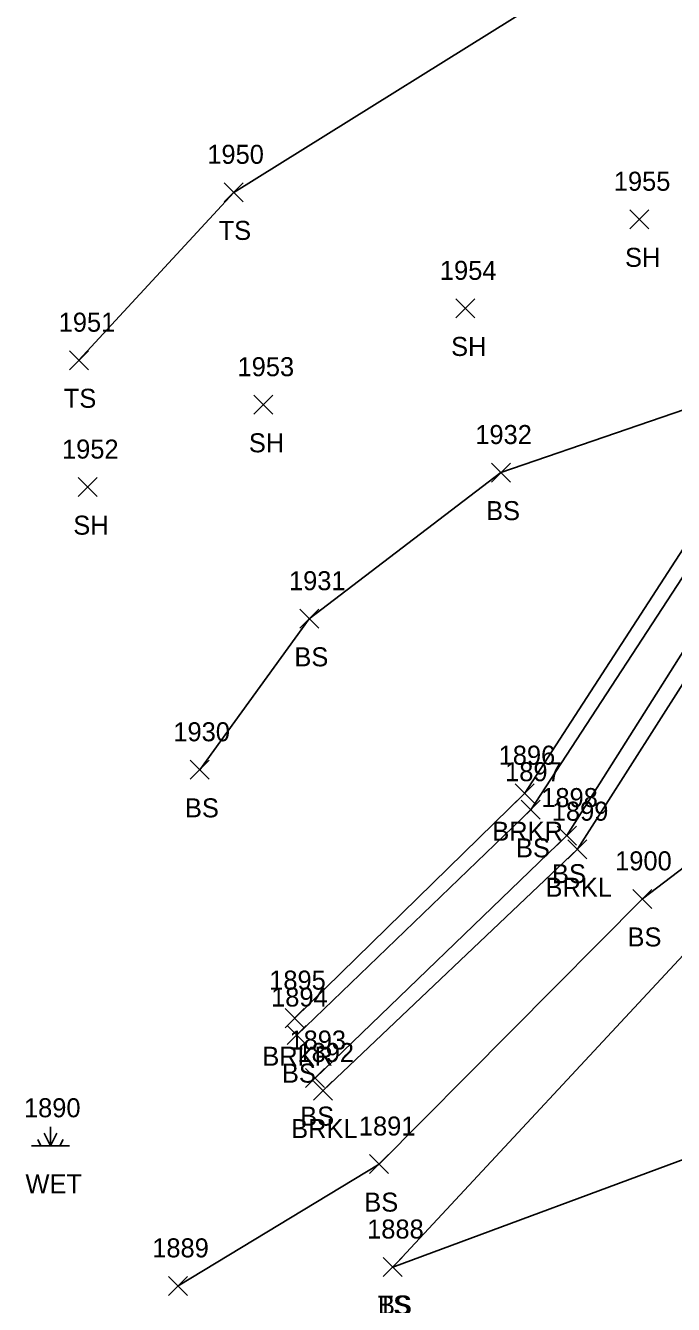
# Model space of a CAD drawing. Extents: x 1885914 to 1887218, y 756253 to 760620.
# Drawn here: x 1886288.7 to 1886356.8, y 759652.9 to 759787.4 of the extents above; entities that cross this region are included whole.
import ezdxf

# ---------------------------------------------------------------- set-up
doc = ezdxf.new("R2010")
doc.units = 0
for name, color, linetype in [('L_A', 7, 'Continuous'), ('L_I', 7, 'Continuous'), ('L_TIC', 7, 'Continuous'), ('LAWE', 7, 'Continuous'), ('LELB', 7, 'Continuous'), ('LWET', 7, 'Continuous')]:
    doc.layers.add(name, color=color, linetype=linetype)

msp = doc.modelspace()

# ---------------------------------------------------------------- linework, layer by layer
at = {"layer": 'L_TIC'}
for points in [[(1886309.58, 759768.85), (1886311.58, 759770.85)], [(1886311.58, 759768.85), (1886309.58, 759770.85)], [(1886352.25, 759766.02), (1886354.25, 759768.02)], [(1886354.25, 759766.02), (1886352.25, 759768.02)], [(1886333.95, 759756.65), (1886335.95, 759758.65)], [(1886335.95, 759756.65), (1886333.95, 759758.65)], [(1886293.3, 759751.2), (1886295.3, 759753.2)], [(1886295.3, 759751.2), (1886293.3, 759753.2)], [(1886312.68, 759746.52), (1886314.68, 759748.52)], [(1886314.68, 759746.52), (1886312.68, 759748.52)], [(1886337.68, 759739.39), (1886339.68, 759741.39)], [(1886339.68, 759739.39), (1886337.68, 759741.39)], [(1886294.22, 759737.86), (1886296.22, 759739.86)], [(1886296.22, 759737.86), (1886294.22, 759739.86)], [(1886317.52, 759724.02), (1886319.52, 759726.02)], [(1886319.52, 759724.02), (1886317.52, 759726.02)], [(1886306, 759708.14), (1886308, 759710.14)], [(1886308, 759708.14), (1886306, 759710.14)], [(1886340.18, 759705.68), (1886342.18, 759707.68)], [(1886342.18, 759705.68), (1886340.18, 759707.68)], [(1886340.81, 759703.94), (1886342.81, 759705.94)], [(1886342.81, 759703.94), (1886340.81, 759705.94)], [(1886344.61, 759701.22), (1886346.61, 759703.22)], [(1886346.61, 759701.22), (1886344.61, 759703.22)], [(1886345.73, 759699.79), (1886347.73, 759701.79)], [(1886347.73, 759699.79), (1886345.73, 759701.79)], [(1886352.55, 759694.57), (1886354.55, 759696.57)], [(1886354.55, 759694.57), (1886352.55, 759696.57)], [(1886316, 759682.03), (1886318, 759684.03)], [(1886318, 759682.03), (1886316, 759684.03)], [(1886316.21, 759680.25), (1886318.21, 759682.25)], [(1886318.21, 759680.25), (1886316.21, 759682.25)], [(1886318.13, 759675.73), (1886320.13, 759677.73)], [(1886320.13, 759675.73), (1886318.13, 759677.73)], [(1886318.97, 759674.42), (1886320.97, 759676.42)], [(1886320.97, 759674.42), (1886318.97, 759676.42)], [(1886324.87, 759666.69), (1886326.87, 759668.69)], [(1886326.87, 759666.69), (1886324.87, 759668.69)], [(1886326.3, 759655.86), (1886328.3, 759657.86)], [(1886328.3, 759655.86), (1886326.3, 759657.86)], [(1886326.3, 759655.86), (1886328.3, 759657.86)], [(1886328.3, 759655.86), (1886326.3, 759657.86)], [(1886303.72, 759653.88), (1886305.72, 759655.88)], [(1886305.72, 759653.88), (1886303.72, 759655.88)]]:
    msp.add_lwpolyline(points, dxfattribs=at)
at = {"layer": 'LAWE'}
for points in [[(1886317, 759683.03), (1886341.18, 759706.68), (1886360.29, 759736.17), (1886364.88, 759738.76), (1886370.21, 759737.83), (1886375.31, 759734.04), (1886391.66, 759750.79), (1886399.84, 759751.25), (1886405.16, 759747.14)], [(1886319.97, 759675.42), (1886346.73, 759700.79), (1886366.11, 759731.21), (1886375.2, 759726.91), (1886379.74, 759726.02), (1886393.91, 759741.19), (1886401.85, 759738.99)]]:
    msp.add_lwpolyline(points, dxfattribs=at)
at = {"layer": 'LELB'}
for points in [[(1886420.59, 759830.9), (1886395.58, 759812.74), (1886365.13, 759802.51), (1886347.14, 759792.66), (1886310.58, 759769.85), (1886294.3, 759752.2)], [(1886307, 759709.14), (1886318.52, 759725.02), (1886338.68, 759740.39), (1886365.24, 759749.52), (1886380.86, 759754.85), (1886394.35, 759762.41), (1886406.37, 759774.36), (1886414.51, 759783.7), (1886422.61, 759797.12), (1886430.75, 759808.98)], [(1886317.21, 759681.25), (1886341.81, 759704.94), (1886361.48, 759735.07), (1886365.13, 759737.99), (1886369.88, 759736.88), (1886375.93, 759732.56), (1886392.43, 759748.73), (1886399.75, 759749.71), (1886405.53, 759745.98)], [(1886319.13, 759676.73), (1886345.61, 759702.22), (1886365.08, 759732.99), (1886376.94, 759728.59), (1886392.47, 759742.78), (1886404.87, 759741.44), (1886405.53, 759745.98)], [(1886304.72, 759654.88), (1886325.87, 759667.69), (1886353.55, 759695.57), (1886377.7, 759713.93), (1886397.18, 759731.7), (1886401.85, 759738.99)], [(1886401.43, 759725.45), (1886391.73, 759716.93), (1886382.2, 759702.66), (1886359.74, 759691.68), (1886327.3, 759656.86)], [(1886359.74, 759691.68), (1886361.34, 759669.47), (1886327.3, 759656.86)]]:
    msp.add_lwpolyline(points, dxfattribs=at)
at = {"layer": 'LWET'}
for p, q in [((1886291.3, 759669.61), (1886290.63, 759670.95)), ((1886291.3, 759669.61), (1886291.3, 759671.61)), ((1886291.3, 759669.61), (1886291.97, 759670.95)), ((1886293.3, 759669.61), (1886289.3, 759669.61)), ((1886290.3, 759669.61), (1886289.97, 759670.28)), ((1886292.3, 759669.61), (1886292.63, 759670.28))]:
    msp.add_line(p, q, dxfattribs=at)

# ---------------------------------------------------------------- texts
at = {"layer": 'L_A'}
for s, p in [('TS', (1886308.99, 759764.85)), ('SH', (1886351.73, 759762.02)), ('SH', (1886333.44, 759752.65)), ('TS', (1886292.71, 759747.2)), ('SH', (1886312.17, 759742.52)), ('BS', (1886337.12, 759735.39)), ('SH', (1886293.71, 759733.86)), ('BS', (1886316.96, 759720.02)), ('BS', (1886305.45, 759704.14)), ('BRKR', (1886337.77, 759701.68)), ('BS', (1886340.26, 759699.94)), ('BS', (1886344.05, 759697.22)), ('BRKL', (1886343.37, 759695.79)), ('BS', (1886351.99, 759690.57)), ('BRKR', (1886313.59, 759678.03)), ('BS', (1886315.65, 759676.25)), ('BS', (1886317.57, 759671.73)), ('BRKL', (1886316.62, 759670.42)), ('WET', (1886288.68, 759664.61)), ('BS', (1886324.31, 759662.69)), ('TS', (1886325.71, 759651.86)), ('BS', (1886325.75, 759651.86))]:
    msp.add_text(s, height=2, dxfattribs=at).set_placement(p)
at = {"layer": 'L_I'}
for s, p in [('1950', (1886307.8, 759772.85)), ('1955', (1886350.55, 759770.02)), ('1954', (1886332.26, 759760.65)), ('1951', (1886292.17, 759755.2)), ('1953', (1886310.98, 759750.52)), ('1932', (1886335.98, 759743.39)), ('1952', (1886292.52, 759741.86)), ('1931', (1886316.39, 759728.02)), ('1930', (1886304.23, 759712.14)), ('1896', (1886338.44, 759709.68)), ('1897', (1886339.12, 759707.94)), ('1898', (1886342.92, 759705.22)), ('1899', (1886344.03, 759703.79)), ('1900', (1886350.69, 759698.57)), ('1895', (1886314.31, 759686.03)), ('1894', (1886314.51, 759684.25)), ('1893', (1886316.44, 759679.73)), ('1892', (1886317.28, 759678.42)), ('1890', (1886288.52, 759672.61)), ('1891', (1886323.74, 759670.69)), ('1888', (1886324.61, 759659.86)), ('1888', (1886324.61, 759659.86)), ('1889', (1886302.01, 759657.88))]:
    msp.add_text(s, height=2, dxfattribs=at).set_placement(p)

doc.saveas('drawing.dxf')
